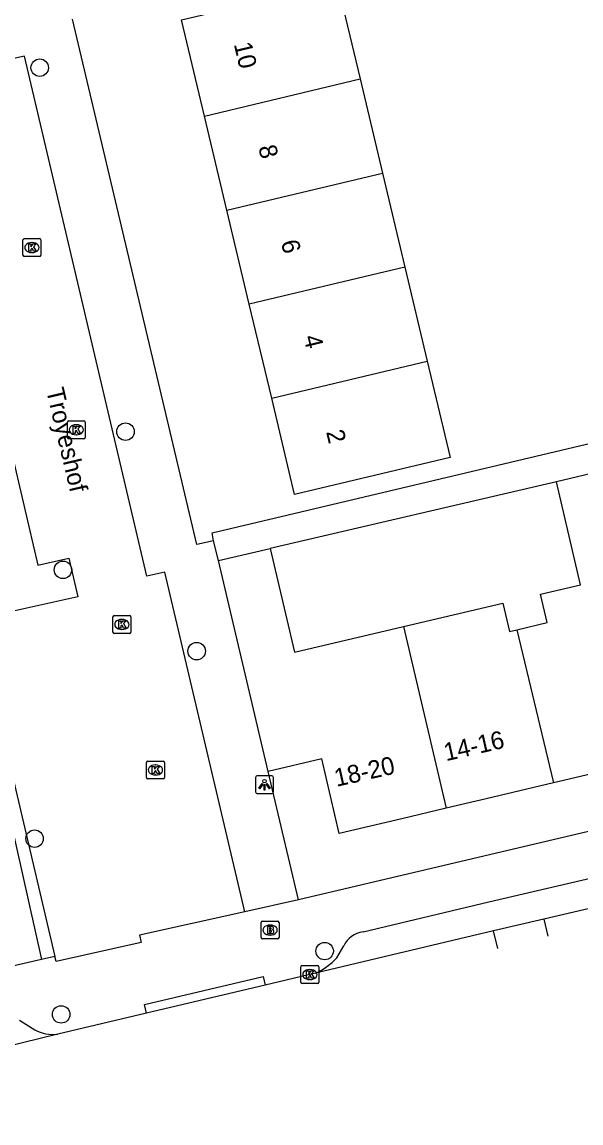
# Model space of a CAD drawing. Extents: x 158474 to 159560, y 388525 to 389605.
# Drawn here: x 159167.2 to 159198.5, y 388548.8 to 388610.4 of the extents above; entities that cross this region are included whole.
import ezdxf

# ---------------------------------------------------------------- set-up
doc = ezdxf.new("R2010")
doc.units = 0
for name, color, linetype in [('IMGEO_Boom', 7, 'Continuous'), ('IMGEO_Brandkraan', 7, 'Continuous'), ('IMGEO_Kolk', 7, 'Continuous'), ('IMGEO_Lichtpunt', 7, 'Continuous'), ('IMGEO_Openbare_ruimte_label', 7, 'Continuous'), ('IMGEO_Pand', 7, 'Continuous'), ('IMGEO_Pand_nummerreeks', 7, 'Continuous'), ('IMGEO_Rijbaan_lokaal_open', 7, 'Continuous'), ('IMGEO_Voetpad_gesloten', 7, 'Continuous'), ('IMGEO_Voetpad_open', 7, 'Continuous')]:
    doc.layers.add(name, color=color, linetype=linetype)

msp = doc.modelspace()

# ---------------------------------------------------------------- linework, layer by layer
at = {"layer": 'IMGEO_Boom'}
for centre in [(159168.228, 388607.851), (159173.023, 388587.499), (159169.525, 388579.773), (159177.004, 388575.227), (159167.939, 388564.744), (159184.157, 388558.456), (159169.426, 388554.915)]:
    msp.add_circle(centre, 0.489, dxfattribs=at)
at = {"layer": 'IMGEO_Brandkraan'}
for p, q in [((159180.608, 388559.207), (159180.608, 388560.059)), ((159180.683, 388560.133), (159181.535, 388560.133)), ((159181.609, 388560.059), (159181.609, 388559.207)), ((159181.096, 388559.913), (159181.121, 388559.913)), ((159181.535, 388559.133), (159180.683, 388559.133)), ((159181.119, 388559.353), (159181.094, 388559.353))]:
    msp.add_line(p, q, dxfattribs=at)
for points in [[(159180.608, 388559.207), (159180.608, 388560.059)], [(159180.683, 388560.133), (159181.535, 388560.133)], [(159181.609, 388560.059), (159181.609, 388559.207)], [(159180.956, 388559.833), (159180.956, 388559.433), (159181.169, 388559.433)], [(159181.187, 388559.833), (159180.956, 388559.833)], [(159181.135, 388559.752), (159181.081, 388559.752), (159181.081, 388559.676)], [(159181.081, 388559.676), (159181.134, 388559.676)], [(159181.143, 388559.6), (159181.081, 388559.6), (159181.081, 388559.519)], [(159181.081, 388559.519), (159181.143, 388559.519)], [(159181.535, 388559.133), (159180.683, 388559.133)]]:
    msp.add_lwpolyline(points, dxfattribs=at)
for centre, radius, start, end in [((159180.685, 388560.057), 0.0765, 91.55205, 178.44795), ((159180.685, 388560.057), 0.0765, 91.55205, 178.44795), ((159181.533, 388560.057), 0.0765, 1.55205, 88.44795), ((159181.533, 388560.057), 0.0765, 1.55205, 88.44795), ((159181.136, 388559.714), 0.0379, 267.82845, 90.93552), ((159181.144, 388559.559), 0.0404, 269.87594, 90.50774), ((159181.175, 388559.684), 0.251, 268.66757, 293.53466), ((159181.191, 388559.688), 0.145, 59.4692, 91.53667), ((159181.216, 388559.735), 0.0922, 285.51372, 58.15012), ((159181.221, 388559.543), 0.105, 301.31148, 78.98903), ((159180.685, 388559.209), 0.0765, 181.55205, 268.44795), ((159180.685, 388559.209), 0.0765, 181.55205, 268.44795), ((159181.533, 388559.209), 0.0765, 271.55205, 358.44795), ((159181.533, 388559.209), 0.0765, 271.55205, 358.44795)]:
    msp.add_arc(centre, radius, start, end, dxfattribs=at)
for centre, major_axis, ratio, start_param, end_param in [((159181.095, 388559.633), (-0.387, 0.002), 0.722429, 4.712389, 7.853982), ((159181.12, 388559.633), (-0.39, 0.002), 0.717154, 1.570796, 4.712389)]:
    msp.add_ellipse(centre, major_axis=major_axis, ratio=ratio, start_param=start_param, end_param=end_param, dxfattribs=at)
at = {"layer": 'IMGEO_Kolk'}
for p, q in [((159167.29, 388597.366), (159167.29, 388598.218)), ((159167.365, 388598.292), (159168.217, 388598.292)), ((159168.291, 388598.218), (159168.291, 388597.366)), ((159167.778, 388598.072), (159167.803, 388598.072)), ((159168.217, 388597.292), (159167.365, 388597.292)), ((159167.801, 388597.512), (159167.776, 388597.512)), ((159169.771, 388587.178), (159169.771, 388588.03)), ((159169.846, 388588.104), (159170.698, 388588.104)), ((159170.259, 388587.884), (159170.284, 388587.884)), ((159170.772, 388588.03), (159170.772, 388587.178)), ((159170.282, 388587.324), (159170.257, 388587.324)), ((159170.698, 388587.104), (159169.846, 388587.104)), ((159172.321, 388576.292), (159172.321, 388577.144)), ((159172.396, 388577.218), (159173.248, 388577.218)), ((159172.809, 388576.998), (159172.834, 388576.998)), ((159173.322, 388577.144), (159173.322, 388576.292)), ((159173.248, 388576.218), (159172.396, 388576.218)), ((159172.832, 388576.438), (159172.807, 388576.438)), ((159174.198, 388568.156), (159174.198, 388569.008)), ((159174.273, 388569.082), (159175.125, 388569.082)), ((159174.686, 388568.862), (159174.711, 388568.862)), ((159175.199, 388569.008), (159175.199, 388568.156)), ((159175.125, 388568.082), (159174.273, 388568.082)), ((159174.709, 388568.302), (159174.684, 388568.302)), ((159182.908, 388557.643), (159183.76, 388557.643)), ((159182.833, 388556.717), (159182.833, 388557.569)), ((159183.321, 388557.423), (159183.346, 388557.423)), ((159183.834, 388557.569), (159183.834, 388556.717)), ((159183.76, 388556.643), (159182.908, 388556.643)), ((159183.344, 388556.863), (159183.319, 388556.863))]:
    msp.add_line(p, q, dxfattribs=at)
for points in [[(159167.29, 388597.366), (159167.29, 388598.218)], [(159167.365, 388598.292), (159168.217, 388598.292)], [(159168.291, 388598.218), (159168.291, 388597.366)], [(159167.611, 388597.992), (159167.734, 388597.992), (159167.734, 388597.841), (159167.864, 388597.992), (159168.028, 388597.992), (159167.882, 388597.841), (159168.035, 388597.592), (159167.883, 388597.592), (159167.798, 388597.756), (159167.734, 388597.689), (159167.734, 388597.592), (159167.611, 388597.592), (159167.611, 388597.992)], [(159168.217, 388597.292), (159167.365, 388597.292)], [(159169.771, 388587.178), (159169.771, 388588.03)], [(159169.846, 388588.104), (159170.698, 388588.104)], [(159170.092, 388587.804), (159170.215, 388587.804), (159170.215, 388587.653), (159170.345, 388587.804), (159170.509, 388587.804), (159170.363, 388587.653), (159170.516, 388587.404), (159170.364, 388587.404), (159170.279, 388587.568), (159170.215, 388587.501), (159170.215, 388587.404), (159170.092, 388587.404), (159170.092, 388587.804)], [(159170.772, 388588.03), (159170.772, 388587.178)], [(159170.698, 388587.104), (159169.846, 388587.104)], [(159172.321, 388576.292), (159172.321, 388577.144)], [(159172.396, 388577.218), (159173.248, 388577.218)], [(159172.642, 388576.918), (159172.765, 388576.918), (159172.765, 388576.767), (159172.895, 388576.918), (159173.059, 388576.918), (159172.913, 388576.767), (159173.066, 388576.518), (159172.914, 388576.518), (159172.829, 388576.682), (159172.765, 388576.615), (159172.765, 388576.518), (159172.642, 388576.518), (159172.642, 388576.918)], [(159173.322, 388577.144), (159173.322, 388576.292)], [(159173.248, 388576.218), (159172.396, 388576.218)], [(159174.198, 388568.156), (159174.198, 388569.008)], [(159174.273, 388569.082), (159175.125, 388569.082)], [(159174.519, 388568.782), (159174.642, 388568.782), (159174.642, 388568.631), (159174.772, 388568.782), (159174.936, 388568.782), (159174.79, 388568.631), (159174.943, 388568.382), (159174.791, 388568.382), (159174.706, 388568.546), (159174.642, 388568.479), (159174.642, 388568.382), (159174.519, 388568.382), (159174.519, 388568.782)], [(159175.199, 388569.008), (159175.199, 388568.156)], [(159175.125, 388568.082), (159174.273, 388568.082)], [(159182.908, 388557.643), (159183.76, 388557.643)], [(159182.833, 388556.717), (159182.833, 388557.569)], [(159183.154, 388557.343), (159183.277, 388557.343), (159183.277, 388557.192), (159183.407, 388557.343), (159183.571, 388557.343), (159183.425, 388557.192), (159183.578, 388556.943), (159183.426, 388556.943), (159183.341, 388557.107), (159183.277, 388557.04), (159183.277, 388556.943), (159183.154, 388556.943), (159183.154, 388557.343)], [(159183.834, 388557.569), (159183.834, 388556.717)], [(159183.76, 388556.643), (159182.908, 388556.643)]]:
    msp.add_lwpolyline(points, dxfattribs=at)
for centre, start, end in [((159167.367, 388598.216), 91.55205, 178.44795), ((159167.367, 388598.216), 91.55205, 178.44795), ((159168.215, 388598.216), 1.55205, 88.44795), ((159168.215, 388598.216), 1.55205, 88.44795), ((159167.367, 388597.368), 181.55205, 268.44795), ((159167.367, 388597.368), 181.55205, 268.44795), ((159168.215, 388597.368), 271.55205, 358.44795), ((159168.215, 388597.368), 271.55205, 358.44795), ((159169.848, 388588.028), 91.55205, 178.44795), ((159169.848, 388588.028), 91.55205, 178.44795), ((159170.696, 388588.028), 1.55205, 88.44795), ((159170.696, 388588.028), 1.55205, 88.44795), ((159169.848, 388587.18), 181.55205, 268.44795), ((159169.848, 388587.18), 181.55205, 268.44795), ((159170.696, 388587.18), 271.55205, 358.44795), ((159170.696, 388587.18), 271.55205, 358.44795), ((159172.398, 388577.142), 91.55205, 178.44795), ((159172.398, 388577.142), 91.55205, 178.44795), ((159173.246, 388577.142), 1.55205, 88.44795), ((159173.246, 388577.142), 1.55205, 88.44795), ((159172.398, 388576.294), 181.55205, 268.44795), ((159172.398, 388576.294), 181.55205, 268.44795), ((159173.246, 388576.294), 271.55205, 358.44795), ((159173.246, 388576.294), 271.55205, 358.44795), ((159174.275, 388569.006), 91.55205, 178.44795), ((159174.275, 388569.006), 91.55205, 178.44795), ((159175.123, 388569.006), 1.55205, 88.44795), ((159175.123, 388569.006), 1.55205, 88.44795), ((159174.275, 388568.158), 181.55205, 268.44795), ((159174.275, 388568.158), 181.55205, 268.44795), ((159175.123, 388568.158), 271.55205, 358.44795), ((159175.123, 388568.158), 271.55205, 358.44795), ((159182.91, 388557.567), 91.55205, 178.44795), ((159182.91, 388557.567), 91.55205, 178.44795), ((159183.758, 388557.567), 1.55205, 88.44795), ((159183.758, 388557.567), 1.55205, 88.44795), ((159182.91, 388556.719), 181.55205, 268.44795), ((159182.91, 388556.719), 181.55205, 268.44795), ((159183.758, 388556.719), 271.55205, 358.44795), ((159183.758, 388556.719), 271.55205, 358.44795)]:
    msp.add_arc(centre, 0.0765, start, end, dxfattribs=at)
for centre, major_axis, ratio, start_param, end_param in [((159167.777, 388597.792), (-0.387, 0.002), 0.722429, 4.712389, 7.853982), ((159167.802, 388597.792), (-0.39, 0.002), 0.717154, 1.570796, 4.712389), ((159170.258, 388587.604), (-0.387, 0.002), 0.722429, 4.712389, 7.853982), ((159170.283, 388587.604), (-0.39, 0.002), 0.717154, 1.570796, 4.712389), ((159172.808, 388576.718), (-0.387, 0.002), 0.722429, 4.712389, 7.853982), ((159172.833, 388576.718), (-0.39, 0.002), 0.717154, 1.570796, 4.712389), ((159174.685, 388568.582), (-0.387, 0.002), 0.722429, 4.712389, 7.853982), ((159174.71, 388568.582), (-0.39, 0.002), 0.717154, 1.570796, 4.712389), ((159183.32, 388557.143), (-0.387, 0.002), 0.722429, 4.712389, 7.853982), ((159183.345, 388557.143), (-0.39, 0.002), 0.717154, 1.570796, 4.712389)]:
    msp.add_ellipse(centre, major_axis=major_axis, ratio=ratio, start_param=start_param, end_param=end_param, dxfattribs=at)
at = {"layer": 'IMGEO_Lichtpunt'}
for p, q in [((159180.3, 388568.161), (159180.3, 388567.354)), ((159180.3, 388568.161), (159180.3, 388567.354)), ((159181.202, 388568.256), (159180.394, 388568.256)), ((159181.202, 388568.256), (159180.394, 388568.256)), ((159181.296, 388567.354), (159181.296, 388568.161)), ((159181.296, 388567.354), (159181.296, 388568.161)), ((159180.394, 388567.26), (159181.202, 388567.26)), ((159180.394, 388567.26), (159181.202, 388567.26))]:
    msp.add_line(p, q, dxfattribs=at)
for points in [[(159180.674, 388567.825), (159180.713, 388567.797), (159180.525, 388567.535), (159180.487, 388567.562), (159180.674, 388567.825)], [(159180.776, 388567.777), (159180.823, 388567.777), (159180.823, 388567.455), (159180.776, 388567.455), (159180.776, 388567.777)], [(159180.886, 388567.797), (159180.924, 388567.824), (159181.111, 388567.562), (159181.072, 388567.534), (159180.886, 388567.797)]]:
    msp.add_lwpolyline(points, dxfattribs=at)
msp.add_circle((159180.799, 388567.959), 0.0994, dxfattribs=at)
for centre, start, end in [((159180.394, 388568.161), 90, 180), ((159180.394, 388568.161), 90, 180), ((159181.202, 388568.161), 0, 90), ((159181.202, 388568.161), 0, 90), ((159180.394, 388567.354), 180, 270), ((159180.394, 388567.354), 180, 270), ((159181.202, 388567.354), 270, 0), ((159181.202, 388567.354), 270, 360)]:
    msp.add_arc(centre, 0.0946, start, end, dxfattribs=at)
at = {"layer": 'IMGEO_Pand'}
for points in [[(159177.442, 388605.147), (159176.161, 388610.525), (159181.025, 388611.683), (159184.861, 388612.597), (159186.142, 388607.219)], [(159177.442, 388605.147), (159186.142, 388607.219)], [(159186.142, 388607.219), (159187.395, 388601.957)], [(159178.695, 388599.886), (159177.442, 388605.147)], [(159178.695, 388599.886), (159187.395, 388601.957)], [(159187.395, 388601.957), (159188.648, 388596.696)], [(159179.948, 388594.624), (159178.695, 388599.886)], [(159188.648, 388596.696), (159179.948, 388594.624)], [(159188.648, 388596.696), (159189.901, 388591.435)], [(159181.201, 388589.363), (159179.948, 388594.624)], [(159189.901, 388591.435), (159191.182, 388586.055), (159187.346, 388585.141), (159182.482, 388583.983), (159181.201, 388589.363)], [(159181.201, 388589.363), (159189.901, 388591.435)], [(159194.9, 388576.419), (159196.607, 388576.821), (159196.233, 388578.412), (159198.476, 388578.94), (159197.12, 388584.695)], [(159199.087, 388585.158), (159197.12, 388584.695)], [(159178.232, 388580.287), (159181.114, 388580.966)], [(159181.114, 388580.966), (159182.479, 388575.171), (159188.571, 388576.606)], [(159181.007, 388568.502), (159178.232, 388580.287)], [(159188.571, 388576.606), (159194.124, 388577.914), (159194.499, 388576.324), (159194.9, 388576.419)], [(159188.571, 388576.606), (159190.964, 388566.447)], [(159194.9, 388576.419), (159196.956, 388567.858)], [(159190.964, 388566.447), (159188.471, 388565.859), (159184.976, 388565.036), (159183.994, 388569.205), (159181.007, 388568.502)], [(159202.836, 388569.243), (159196.956, 388567.858)], [(159196.956, 388567.858), (159193.194, 388566.972), (159190.964, 388566.447)]]:
    msp.add_lwpolyline(points, dxfattribs=at)
at = {"layer": 'IMGEO_Rijbaan_lokaal_open'}
for points in [[(159179.702, 388560.654), (159175.232, 388579.635), (159174.222, 388579.412), (159167.373, 388608.491), (159161.72, 388607.241), (159164.57, 388595.141), (159166.293, 388595.522), (159166.762, 388593.532), (159165.038, 388593.151), (159168.127, 388580.036), (159169.851, 388580.417), (159170.357, 388578.269), (159164.637, 388577.004), (159169.077, 388558.152)], [(159210.58, 388563.555), (159210.148, 388563.452), (159196.414, 388560.248)], [(159179.702, 388560.654), (159173.799, 388559.349), (159173.898, 388558.93), (159169.142, 388557.878), (159169.077, 388558.152)], [(159196.414, 388560.248), (159193.609, 388559.593)], [(159196.414, 388560.248), (159196.64, 388559.294)], [(159193.609, 388559.593), (159183.651, 388557.219)], [(159193.843, 388558.605), (159193.843, 388558.605), (159193.609, 388559.593)], [(159183.651, 388557.219), (159180.83, 388556.547)], [(159180.83, 388556.547), (159174.19, 388554.983)], [(159174.19, 388554.983), (159169.234, 388553.816)], [(159169.234, 388553.816), (159149.019, 388548.845)]]:
    msp.add_lwpolyline(points, dxfattribs=at)
at = {"layer": 'IMGEO_Voetpad_gesloten'}
msp.add_lwpolyline([(159174.19, 388554.983), (159174.08, 388555.47), (159180.72, 388557.034), (159180.83, 388556.547)], dxfattribs=at)
at = {"layer": 'IMGEO_Voetpad_open'}
for points in [[(159177.94, 388581.388), (159177.021, 388581.185), (159170.055, 388610.56)], [(159177.94, 388581.388), (159177.865, 388581.835), (159208.71, 388589.15), (159208.535, 388589.892)], [(159197.12, 388584.695), (159181.114, 388580.966)], [(159178.232, 388580.287), (159177.94, 388581.388)], [(159164.088, 388576.829), (159168.333, 388557.977)], [(159245.514, 388576.124), (159182.704, 388561.32)], [(159182.704, 388561.32), (159181.007, 388568.502)], [(159186.305, 388559.536), (159193.346, 388561.214), (159207.586, 388564.536)], [(159182.704, 388561.32), (159179.702, 388560.654)], [(159184.837, 388558.081), (159185.224, 388558.749)], [(159168.333, 388557.977), (159149.026, 388553.544)], [(159169.077, 388558.152), (159168.333, 388557.977)], [(159167.098, 388554.601), (159167.951, 388554.059)]]:
    msp.add_lwpolyline(points, dxfattribs=at)
for centre, radius, start, end in [((159186.512, 388558.116), 1.435, 98.27843, 153.83302), ((159182.242, 388560.405), 3.484, 293.86233, 318.15794), ((159168.945, 388555.797), 2.002, 240.24478, 278.30567)]:
    msp.add_arc(centre, radius, start, end, dxfattribs=at)

# ---------------------------------------------------------------- texts
at = {"layer": 'IMGEO_Openbare_ruimte_label'}
msp.add_text('Troyeshof', height=1, rotation=283.2438, dxfattribs=at).set_placement((159168.58, 388589.829))
at = {"layer": 'IMGEO_Pand_nummerreeks'}
for s, rotation, p in [('10', 283.39551, (159179.075, 388609.167)), ('8', 283.39551, (159180.445, 388603.41)), ('6', 283.39551, (159181.709, 388598.106)), ('4', 283.39551, (159182.973, 388592.797)), ('2', 283.39551, (159184.237, 388587.491)), ('14-16', 12.84965, (159190.945, 388569.07)), ('18-20', 12.70273, (159184.821, 388567.639))]:
    msp.add_text(s, height=1, rotation=rotation, dxfattribs=at).set_placement(p)

doc.saveas('drawing.dxf')
